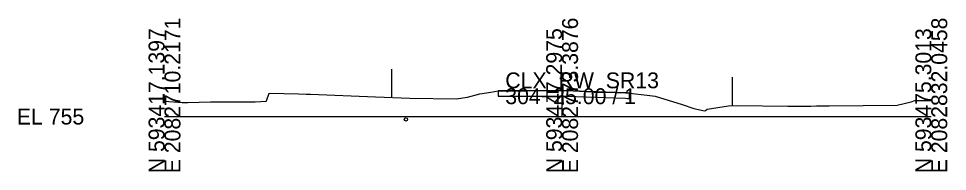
# Model space of a CAD drawing. Extents: x -26 to 2138, y -10 to 4518.
# Drawn here: x 974.3 to 1137.8, y 4490.3 to 4517.3 of the extents above; entities that cross this region are included whole.
import ezdxf

# ---------------------------------------------------------------- set-up
doc = ezdxf.new("R2010")
doc.units = 0
for name, color, linetype in [('GK_Cells', 7, 'Continuous'), ('MD_X_Asphalt_Pavement', 7, 'Continuous'), ('RW_X_Esmt_SH', 7, 'Continuous'), ('UT_X_Water', 7, 'Continuous'), ('XS_X_Ground_Line', 7, 'Continuous')]:
    doc.layers.add(name, color=color, linetype=linetype)

msp = doc.modelspace()

# ---------------------------------------------------------------- linework, layer by layer
at = {"layer": 'GK_Cells'}
for p, q in [((1070, 4500), (1070, 4505)), ((1000, 4500), (1070, 4500)), ((1070, 4500), (1135, 4500))]:
    msp.add_line(p, q, dxfattribs=at)
at = {"layer": 'MD_X_Asphalt_Pavement'}
msp.add_lwpolyline([(1060, 4504.54), (1058.73, 4504.55), (1058.73, 4503.59), (1060, 4503.58), (1060.49, 4503.58), (1063.9, 4503.6), (1070.75, 4503.63), (1074.21, 4503.5), (1081.19, 4503.24), (1081.54, 4503.21), (1081.86, 4503.17), (1081.86, 4504.13), (1081.54, 4504.17), (1081.19, 4504.2), (1074.21, 4504.46), (1070.75, 4504.59), (1063.9, 4504.56), (1060.49, 4504.54), (1060, 4504.54)], dxfattribs=at)
at = {"layer": 'RW_X_Esmt_SH'}
for p, q in [((1040, 4503.38), (1040, 4508.38)), ((1100, 4501.94), (1100, 4506.94))]:
    msp.add_line(p, q, dxfattribs=at)
at = {"layer": 'UT_X_Water'}
msp.add_circle((1042.5, 4499.5), 0.3, dxfattribs=at)
at = {"layer": 'XS_X_Ground_Line'}
msp.add_lwpolyline([(1000, 4502.74), (1003.09, 4502.51), (1004.08, 4502.48), (1008.1, 4502.59), (1015.95, 4502.6), (1017.97, 4502.75), (1017.98, 4502.8), (1018.43, 4504.15), (1023.59, 4504.02), (1024.92, 4503.99), (1025.01, 4503.99), (1025.53, 4503.98), (1025.69, 4503.97), (1037.15, 4503.47), (1043.19, 4503.27), (1051.34, 4503.12), (1053.37, 4503.45), (1055.51, 4504.04), (1057.47, 4504.31), (1058.73, 4504.55), (1060, 4504.54), (1060.49, 4504.54), (1063.9, 4504.56), (1070.75, 4504.59), (1074.21, 4504.46), (1081.19, 4504.2), (1081.54, 4504.17), (1081.86, 4504.13), (1084.96, 4503.8), (1086.36, 4503.63), (1091.15, 4502.11), (1093.18, 4501.44), (1095.05, 4501.04), (1095.24, 4501.07), (1095.56, 4501.29), (1099.3, 4501.93), (1100.86, 4501.95), (1109.73, 4501.86), (1113.82, 4501.87), (1114.79, 4501.88), (1116.33, 4501.89), (1117.02, 4501.9), (1128.97, 4502.02), (1131.48, 4502.58), (1132.1, 4502.84), (1135, 4502.84)], dxfattribs=at)

# ---------------------------------------------------------------- texts
msp.add_text('-', height=0.0001).set_placement((1000, 4500))
at = {"layer": 'GK_Cells'}
for s, p in [('E 2082710.2171', (1002.8, 4490)), ('E 2082773.3876', (1072.8, 4490)), ('E 2082832.0458', (1137.8, 4490)), ('N 593417.1397', (1000, 4490)), ('N 593447.2975', (1070, 4490)), ('N 593475.3013', (1135, 4490))]:
    msp.add_text(s, height=2.8, rotation=90, dxfattribs=at).set_placement(p)
for s, p in [('CLX_RW_SR13', (1060, 4505)), ('304+25.00 / 1', (1060, 4502.2)), ('EL 755', (974, 4498.6))]:
    msp.add_text(s, height=2.8, dxfattribs=at).set_placement(p)

doc.saveas('drawing.dxf')
